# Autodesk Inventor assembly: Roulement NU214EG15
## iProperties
Shininess: 64.0
Length Units: 11269
Angle Units: 11279
Time Units: 11290
Mass Units: 11283
Length Display Precision: 3
Angle Display Precision: 2
Compacted: True
Created: 2005-02
Part Number: Roulement NU214EG15
Document SubType Name: Assembly
Designer: LEGERET Philippe
Catalog Web Link: www.traceparts.com
Description: Roulement à rouleaux cylindriques type NU - pour arbre Ø70
Vendor: SNR
Density: 0.0
Volumn: 0.0
Area: 0.0
PropertySet Name: Model Information
Control State: 0
Master: False
Checked Out: False
REFERENCE: NU214EG15
MASS: 1.17
Author: Trace Parts S.A.
